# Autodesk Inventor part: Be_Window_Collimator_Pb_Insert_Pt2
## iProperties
Shininess: 64.0
Length Units: 11269
Angle Units: 11279
Time Units: 11290
Mass Units: 11283
Length Display Precision: 3
Angle Display Precision: 2
Compacted: True
Part Number: Be_Window_Collimator_Pb_Insert_Pt2
Document SubType Name: Sheet Metal
Created: 2004-07
Material: Lead
Designer: John Blackburn
Manufacturer: Standard
Standards Organization: Custom
Density: 0.0
Volumn: 0.0
Area: 0.0
PropertySet Name: Model Information
Control State: 0
Master: False
Checked Out: False
Author: John Blackburn
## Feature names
1. Revolution1
